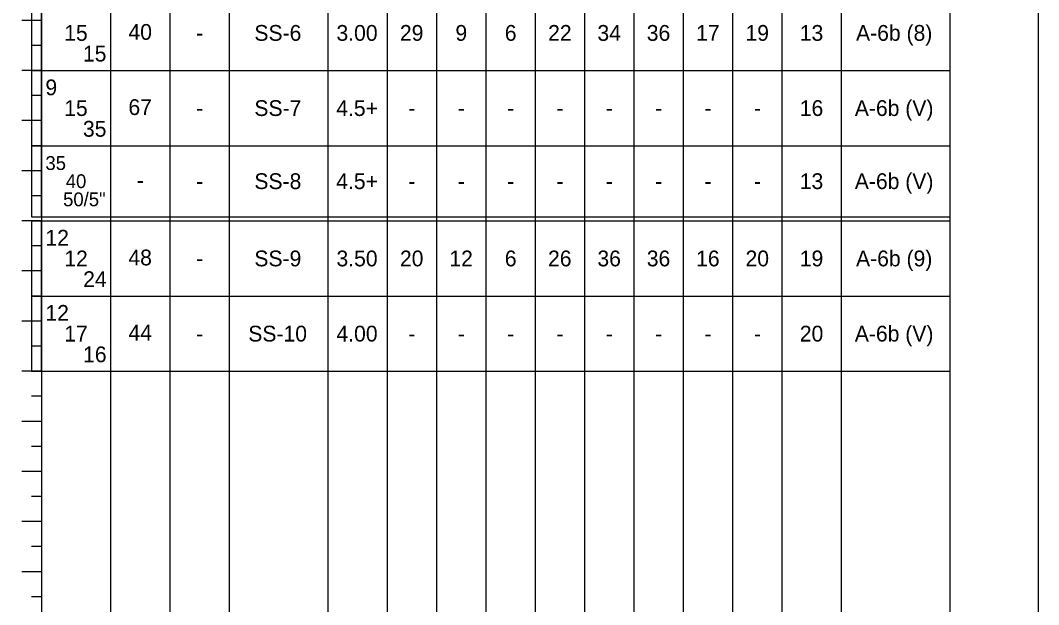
# Model space of a CAD drawing. Extents: x 0 to 0.833, y -0.381 to 0.608.
# Drawn here: x 0.4036 to 0.8333, y 0.1131 to 0.3598 of the extents above; entities that cross this region are included whole.
import ezdxf

# ---------------------------------------------------------------- set-up
doc = ezdxf.new("R2010")
doc.units = 0

msp = doc.modelspace()

# ---------------------------------------------------------------- linework, layer by layer
for points in [[(0, -0.38086), (0.83333, -0.38086), (0.83333, 0.60833), (0, 0.60833)], [(0.40833, 0.33867), (0.4125, 0.33867), (0.4125, 0.37042), (0.40833, 0.37042)], [(0.40833, 0.30692), (0.4125, 0.30692), (0.4125, 0.33867), (0.40833, 0.33867)], [(0.40833, 0.27693), (0.4125, 0.27693), (0.4125, 0.30692), (0.40833, 0.30692)], [(0.40833, 0.24342), (0.4125, 0.24342), (0.4125, 0.27517), (0.40833, 0.27517)], [(0.40833, 0.21167), (0.4125, 0.21167), (0.4125, 0.24342), (0.40833, 0.24342)]]:
    msp.add_lwpolyline(points, close=True)
for points in [[(0.4125, 0.55417), (0.4125, -0.33867)], [(0.4125, 0.55417), (0.4125, -0.33867)], [(0.44167, 0.55417), (0.44167, -0.33867)], [(0.46667, 0.55417), (0.46667, -0.33867)], [(0.49167, 0.55417), (0.49167, -0.33867)], [(0.53333, 0.55417), (0.53333, -0.33867)], [(0.55833, 0.55417), (0.55833, -0.33867)], [(0.6625, 0.55417), (0.6625, -0.33867)], [(0.725, 0.55417), (0.725, -0.33867)], [(0.75, 0.55417), (0.75, -0.33867)], [(0.75, 0.55417), (0.75, -0.33867)], [(0.79583, 0.55417), (0.79583, -0.33867)], [(0.57917, 0.54167), (0.57917, -0.33867)], [(0.6, 0.54167), (0.6, -0.33867)], [(0.62083, 0.54167), (0.62083, -0.33867)], [(0.64167, 0.54167), (0.64167, -0.33867)], [(0.68333, 0.54167), (0.68333, -0.33867)], [(0.70417, 0.54167), (0.70417, -0.33867)], [(0.725, 0.54167), (0.725, -0.33867)], [(0.40833, 0.37042), (0.40833, 0.33867)], [(0.4125, 0.35983), (0.40417, 0.35983)], [(0.4125, 0.35983), (0.40833, 0.35983)], [(0.4125, 0.34925), (0.40833, 0.34925)], [(0.4125, 0.33867), (0.40417, 0.33867)], [(0.40833, 0.33867), (0.4125, 0.33867)], [(0.40833, 0.33867), (0.40833, 0.30692)], [(0.40833, 0.33867), (0.4125, 0.33867)], [(0.4125, 0.33867), (0.40833, 0.33867)], [(0.4125, 0.33867), (0.44167, 0.33867)], [(0.44167, 0.33867), (0.46667, 0.33867)], [(0.46667, 0.33867), (0.49167, 0.33867)], [(0.49167, 0.33867), (0.53333, 0.33867)], [(0.53333, 0.33867), (0.55833, 0.33867)], [(0.55833, 0.33867), (0.57917, 0.33867)], [(0.57917, 0.33867), (0.6, 0.33867)], [(0.6, 0.33867), (0.62083, 0.33867)], [(0.62083, 0.33867), (0.64167, 0.33867)], [(0.64167, 0.33867), (0.6625, 0.33867)], [(0.6625, 0.33867), (0.68333, 0.33867)], [(0.68333, 0.33867), (0.70417, 0.33867)], [(0.70417, 0.33867), (0.725, 0.33867)], [(0.725, 0.33867), (0.75, 0.33867)], [(0.75, 0.33867), (0.79583, 0.33867)], [(0.4125, 0.32808), (0.40833, 0.32808)], [(0.4125, 0.3175), (0.40417, 0.3175)], [(0.4125, 0.3175), (0.40833, 0.3175)], [(0.40833, 0.30692), (0.4125, 0.30692)], [(0.40833, 0.30692), (0.40833, 0.27693)], [(0.40833, 0.30692), (0.4125, 0.30692)], [(0.4125, 0.30692), (0.40833, 0.30692)], [(0.4125, 0.30692), (0.44167, 0.30692)], [(0.44167, 0.30692), (0.46667, 0.30692)], [(0.46667, 0.30692), (0.49167, 0.30692)], [(0.49167, 0.30692), (0.53333, 0.30692)], [(0.53333, 0.30692), (0.55833, 0.30692)], [(0.55833, 0.30692), (0.57917, 0.30692)], [(0.57917, 0.30692), (0.6, 0.30692)], [(0.6, 0.30692), (0.62083, 0.30692)], [(0.62083, 0.30692), (0.64167, 0.30692)], [(0.64167, 0.30692), (0.6625, 0.30692)], [(0.6625, 0.30692), (0.68333, 0.30692)], [(0.68333, 0.30692), (0.70417, 0.30692)], [(0.70417, 0.30692), (0.725, 0.30692)], [(0.725, 0.30692), (0.75, 0.30692)], [(0.75, 0.30692), (0.79583, 0.30692)], [(0.4125, 0.29633), (0.40417, 0.29633)], [(0.4125, 0.29633), (0.40833, 0.29633)], [(0.4125, 0.28575), (0.40833, 0.28575)], [(0.4125, 0.27517), (0.40417, 0.27517)], [(0.40833, 0.27693), (0.4125, 0.27693)], [(0.40833, 0.27517), (0.40833, 0.24342)], [(0.40833, 0.27517), (0.4125, 0.27517)], [(0.4125, 0.27517), (0.40833, 0.27517)], [(0.4125, 0.27693), (0.44167, 0.27693)], [(0.4125, 0.27517), (0.44167, 0.27517)], [(0.44167, 0.27693), (0.46667, 0.27693)], [(0.44167, 0.27517), (0.46667, 0.27517)], [(0.46667, 0.27693), (0.49167, 0.27693)], [(0.46667, 0.27517), (0.49167, 0.27517)], [(0.49167, 0.27693), (0.53333, 0.27693)], [(0.49167, 0.27517), (0.53333, 0.27517)], [(0.53333, 0.27693), (0.55833, 0.27693)], [(0.53333, 0.27517), (0.55833, 0.27517)], [(0.55833, 0.27693), (0.57917, 0.27693)], [(0.55833, 0.27517), (0.57917, 0.27517)], [(0.57917, 0.27693), (0.6, 0.27693)], [(0.57917, 0.27517), (0.6, 0.27517)], [(0.6, 0.27693), (0.62083, 0.27693)], [(0.6, 0.27517), (0.62083, 0.27517)], [(0.62083, 0.27693), (0.64167, 0.27693)], [(0.62083, 0.27517), (0.64167, 0.27517)], [(0.64167, 0.27693), (0.6625, 0.27693)], [(0.64167, 0.27517), (0.6625, 0.27517)], [(0.6625, 0.27693), (0.68333, 0.27693)], [(0.6625, 0.27517), (0.68333, 0.27517)], [(0.68333, 0.27693), (0.70417, 0.27693)], [(0.68333, 0.27517), (0.70417, 0.27517)], [(0.70417, 0.27693), (0.725, 0.27693)], [(0.70417, 0.27517), (0.725, 0.27517)], [(0.725, 0.27693), (0.75, 0.27693)], [(0.725, 0.27517), (0.75, 0.27517)], [(0.75, 0.27693), (0.79583, 0.27693)], [(0.75, 0.27517), (0.79583, 0.27517)], [(0.4125, 0.26458), (0.40833, 0.26458)], [(0.4125, 0.254), (0.40417, 0.254)], [(0.4125, 0.254), (0.40833, 0.254)], [(0.40833, 0.24342), (0.4125, 0.24342)], [(0.40833, 0.24342), (0.40833, 0.21167)], [(0.40833, 0.24342), (0.4125, 0.24342)], [(0.4125, 0.24342), (0.40833, 0.24342)], [(0.4125, 0.24342), (0.44167, 0.24342)], [(0.44167, 0.24342), (0.46667, 0.24342)], [(0.46667, 0.24342), (0.49167, 0.24342)], [(0.49167, 0.24342), (0.53333, 0.24342)], [(0.53333, 0.24342), (0.55833, 0.24342)], [(0.55833, 0.24342), (0.57917, 0.24342)], [(0.57917, 0.24342), (0.6, 0.24342)], [(0.6, 0.24342), (0.62083, 0.24342)], [(0.62083, 0.24342), (0.64167, 0.24342)], [(0.64167, 0.24342), (0.6625, 0.24342)], [(0.6625, 0.24342), (0.68333, 0.24342)], [(0.68333, 0.24342), (0.70417, 0.24342)], [(0.70417, 0.24342), (0.725, 0.24342)], [(0.725, 0.24342), (0.75, 0.24342)], [(0.75, 0.24342), (0.79583, 0.24342)], [(0.4125, 0.23283), (0.40417, 0.23283)], [(0.4125, 0.23283), (0.40833, 0.23283)], [(0.4125, 0.22225), (0.40833, 0.22225)], [(0.4125, 0.21167), (0.40417, 0.21167)], [(0.40833, 0.21167), (0.4125, 0.21167)], [(0.4125, 0.21167), (0.40833, 0.21167)], [(0.4125, 0.21167), (0.44167, 0.21167)], [(0.44167, 0.21167), (0.46667, 0.21167)], [(0.46667, 0.21167), (0.49167, 0.21167)], [(0.49167, 0.21167), (0.53333, 0.21167)], [(0.53333, 0.21167), (0.55833, 0.21167)], [(0.55833, 0.21167), (0.57917, 0.21167)], [(0.57917, 0.21167), (0.6, 0.21167)], [(0.6, 0.21167), (0.62083, 0.21167)], [(0.62083, 0.21167), (0.64167, 0.21167)], [(0.64167, 0.21167), (0.6625, 0.21167)], [(0.6625, 0.21167), (0.68333, 0.21167)], [(0.68333, 0.21167), (0.70417, 0.21167)], [(0.70417, 0.21167), (0.725, 0.21167)], [(0.725, 0.21167), (0.75, 0.21167)], [(0.75, 0.21167), (0.79583, 0.21167)], [(0.4125, 0.20108), (0.40833, 0.20108)], [(0.4125, 0.1905), (0.40417, 0.1905)], [(0.4125, 0.1905), (0.40833, 0.1905)], [(0.4125, 0.17992), (0.40833, 0.17992)], [(0.4125, 0.16933), (0.40417, 0.16933)], [(0.4125, 0.16933), (0.40833, 0.16933)], [(0.4125, 0.15875), (0.40833, 0.15875)], [(0.4125, 0.14817), (0.40417, 0.14817)], [(0.4125, 0.14817), (0.40833, 0.14817)], [(0.4125, 0.13758), (0.40833, 0.13758)], [(0.4125, 0.127), (0.40417, 0.127)], [(0.4125, 0.127), (0.40833, 0.127)], [(0.4125, 0.11642), (0.40833, 0.11642)]]:
    msp.add_lwpolyline(points)

# ---------------------------------------------------------------- texts
for s, height, p in [('15', 0.006667, (0.42209, 0.35121)), ('40', 0.006667, (0.44921, 0.35162)), ('SS-6', 0.006667, (0.50236, 0.35121)), ('3.00', 0.006667, (0.537, 0.35121)), ('29', 0.006667, (0.56378, 0.35121)), ('9', 0.00667, (0.5872, 0.35121)), ('6', 0.00667, (0.60804, 0.35121)), ('22', 0.006667, (0.62632, 0.35121)), ('34', 0.006667, (0.64713, 0.35121)), ('36', 0.006667, (0.66795, 0.35121)), ('17', 0.006667, (0.68878, 0.35121)), ('19', 0.006667, (0.70961, 0.35121)), ('13', 0.006667, (0.73253, 0.35121)), ('A-6b (8)', 0.006667, (0.75627, 0.35121)), ('-', 0.00667, (0.47776, 0.35121)), ('15', 0.006667, (0.43001, 0.34246)), ('9', 0.00667, (0.41417, 0.32821)), ('67', 0.006667, (0.4492, 0.31987)), ('15', 0.006667, (0.42209, 0.31946)), ('-', 0.00667, (0.47776, 0.31946)), ('SS-7', 0.006667, (0.50236, 0.31946)), ('4.5+', 0.006667, (0.5369, 0.31946)), ('-', 0.00667, (0.56734, 0.31946)), ('-', 0.00667, (0.58818, 0.31946)), ('-', 0.00667, (0.60901, 0.31946)), ('-', 0.00667, (0.62984, 0.31946)), ('-', 0.00667, (0.65068, 0.31946)), ('-', 0.00667, (0.67151, 0.31946)), ('-', 0.00667, (0.69234, 0.31946)), ('-', 0.00667, (0.71318, 0.31946)), ('16', 0.006667, (0.73253, 0.31946)), ('A-6b (V)', 0.006667, (0.75575, 0.31946)), ('35', 0.006667, (0.43001, 0.31071)), ('35', 0.005833, (0.41417, 0.29666)), ('40', 0.005833, (0.42275, 0.28901)), ('SS-8', 0.006667, (0.50235, 0.28859)), ('4.5+', 0.006667, (0.5369, 0.28859)), ('13', 0.006667, (0.73253, 0.28859)), ('A-6b (V)', 0.006667, (0.75575, 0.28859)), ('-', 0.00667, (0.45276, 0.28901)), ('-', 0.00667, (0.47776, 0.28859)), ('-', 0.00667, (0.56734, 0.28859)), ('-', 0.00667, (0.58818, 0.28859)), ('-', 0.00667, (0.60901, 0.28859)), ('-', 0.00667, (0.62984, 0.28859)), ('-', 0.00667, (0.65068, 0.28859)), ('-', 0.00667, (0.67151, 0.28859)), ('-', 0.00667, (0.69234, 0.28859)), ('-', 0.00667, (0.71318, 0.28859)), ('50/5"', 0.005833, (0.42163, 0.28135)), ('12', 0.006667, (0.41417, 0.26471)), ('12', 0.006667, (0.42215, 0.25596)), ('48', 0.006667, (0.44919, 0.25637)), ('SS-9', 0.006667, (0.50235, 0.25596)), ('3.50', 0.006667, (0.537, 0.25596)), ('20', 0.006667, (0.56379, 0.25596)), ('12', 0.006667, (0.58465, 0.25596)), ('6', 0.00667, (0.60804, 0.25596)), ('26', 0.006667, (0.62628, 0.25596)), ('36', 0.006667, (0.64712, 0.25596)), ('36', 0.006667, (0.66795, 0.25596)), ('16', 0.006667, (0.68878, 0.25596)), ('20', 0.006667, (0.70963, 0.25596)), ('19', 0.006667, (0.73253, 0.25596)), ('A-6b (9)', 0.006667, (0.75627, 0.25596)), ('-', 0.00667, (0.47776, 0.25596)), ('24', 0.006667, (0.4301, 0.24721)), ('12', 0.006667, (0.41417, 0.23296)), ('17', 0.006667, (0.42212, 0.22421)), ('44', 0.006667, (0.44921, 0.22462)), ('SS-10', 0.006667, (0.49978, 0.22421)), ('4.00', 0.006667, (0.537, 0.22421)), ('20', 0.006667, (0.73254, 0.22421)), ('A-6b (V)', 0.006667, (0.75575, 0.22421)), ('-', 0.00667, (0.47776, 0.22421)), ('-', 0.00667, (0.56734, 0.22421)), ('-', 0.00667, (0.58818, 0.22421)), ('-', 0.00667, (0.60901, 0.22421)), ('-', 0.00667, (0.62984, 0.22421)), ('-', 0.00667, (0.65068, 0.22421)), ('-', 0.00667, (0.67151, 0.22421)), ('-', 0.00667, (0.69234, 0.22421)), ('-', 0.00667, (0.71318, 0.22421)), ('16', 0.006667, (0.43007, 0.21546))]:
    msp.add_text(s, height=height).set_placement(p)

doc.saveas('drawing.dxf')
